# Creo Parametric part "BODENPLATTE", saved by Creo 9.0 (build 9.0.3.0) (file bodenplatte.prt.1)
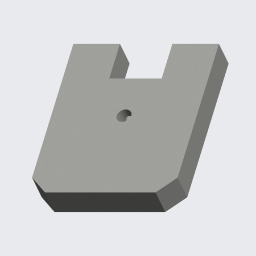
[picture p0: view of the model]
Units: millimeter Kilogram Sec (mmKs); MM, KILOGRAM, SECS
Materials in the file: STAHL

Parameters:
  SCHRAUBEN_GROESSE = "M6x1"
  METRISCH = "JA"
  WERKSTOFF = "Stahl"
  ERSTELLER = "ARINDA"
  BENENNUNG = "Bodenplatte"
  TEILETYP = "K"
  PTC_MASTER_MATERIAL = "STAHL"

Other parameters: STEIGUNG, BOHR_DURCHM, GEWINDEDURCHMESSER, GEWINDEGÄNGE_PRO_INCH, MASSE, GEWINDETIEFE, GEWINDELÄNGE

Created from: ARINDA_STARTTEIL.PRT

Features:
  1. coordinate system
  2. datum plane "RECHTS_Y-Z"
  3. datum plane "OBEN_X-Z"
  4. datum plane "VORNE_X-Y"
  5. datum axis
  6. datum axis
  7. datum axis
  8. datum point "PNT0"
  9. extrusion "Profil 1"
  10. extruded cut "Profil 2"
  11. hole "Bohrung 1"
  12. hole "Bohrung 2"
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
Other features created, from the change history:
  coordinate system "CS1"
  chamfer "Fase 1"

Other named items: GRUNDPLATTE, AUSBRUCH-STÄNDER, TISCHVERSTELLUNG, STÄNDERBEFESTIGUNG, A_X, A_Y, A_Z, CS0

Layers: 01_ACHSEN, 01_ACHSEN_STD, 01_EBENEN_STD, 01_KOORDSYS_STD, 01_PUNKTE_STD, GEWINDE, SAMMELFLÄCHEN, VOLUMENGEOMETRIE

Notes: M6x1 | GEWINDEBOHREN | DURCH |  BOHREN (  | 5.000 | DURCH |   -(  |  ) BOHRUNG | M4x.7 | GEWINDEBOHREN | 8.000 |  BOHREN (  | 3.300 | DURCH |   -(  |  ) BOHRUNG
